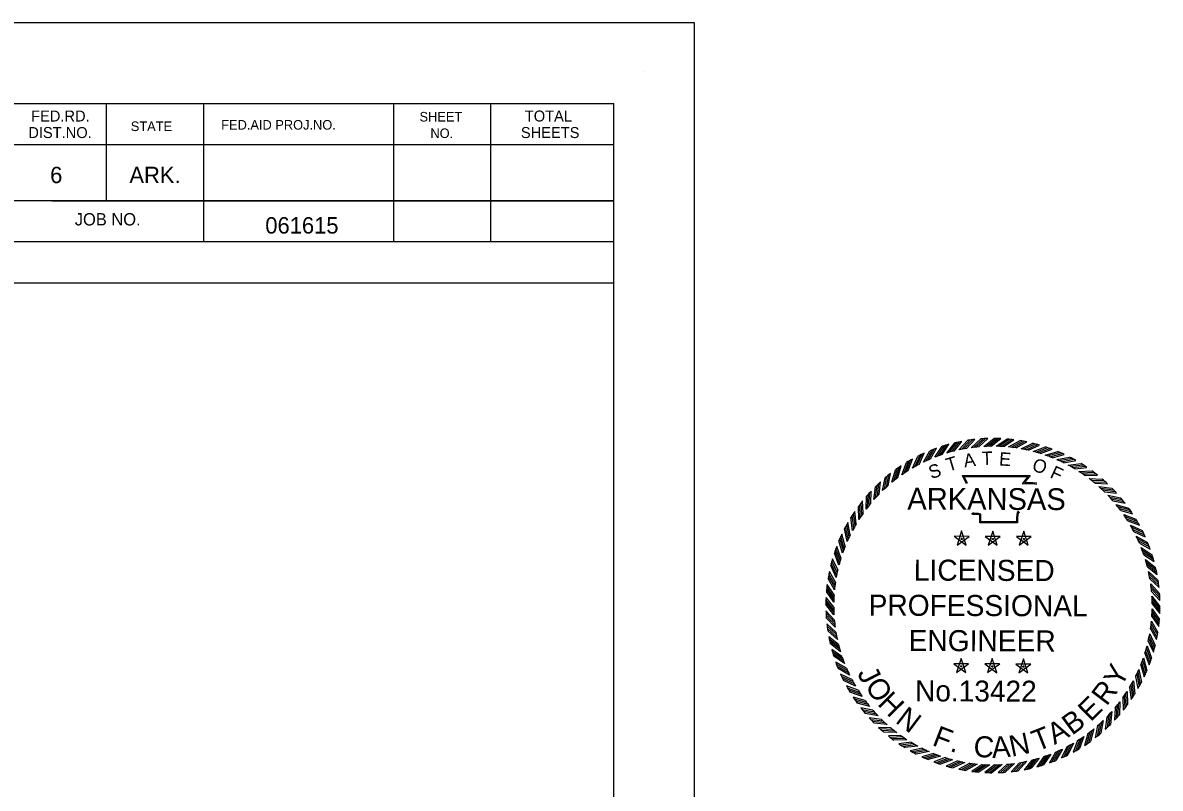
# Model space of a CAD drawing. Extents: x 759422 to 1448857, y 1662254 to 2059437.
# Drawn here: x 1448448.5 to 1448854.7, y 2059163.3 to 2059436.5 of the extents above; entities that cross this region are included whole.
import ezdxf

# ---------------------------------------------------------------- set-up
doc = ezdxf.new("R2010")
doc.units = 0
doc.layers.add('1', color=7, linetype='Continuous')
doc.layers.add('Default', color=7, linetype='Continuous')

# ---------------------------------------------------------------- blocks, each defined once
blk = doc.blocks.new('STAR')
at = {"layer": 'Default'}
for p, q in [((0.0587, 0.0188), (-0.059, 0.0189)), ((-0.0589, 0.0188), (0.0363, -0.0505)), ((-0.0001, 0.0615), (-0.0366, -0.0504)), ((-0.0365, -0.0503), (0.0589, 0.0188)), ((-0.0085, 0), (0.009, 0)), ((0.0362, -0.0503), (0, 0.0617)), ((0, 0.0063), (0, -0.0085))]:
    blk.add_line(p, q, dxfattribs=at)
blk = doc.blocks.new('RP')
at = {"layer": 'Default'}
for p, q in [((-0.0781, 1.2656), (0.003, 1.33)), ((-0.058, 1.2667), (0.0216, 1.3299)), ((-0.0375, 1.2674), (0.0405, 1.3294)), ((-0.0176, 1.2679), (0.059, 1.3287))]:
    blk.add_line(p, q, dxfattribs=at)
for radius, start, end in [(1.268, 90.79335, 93.53072), (1.33, 87.45624, 89.86992)]:
    blk.add_arc((0, 0), radius, start, end, dxfattribs=at)

msp = doc.modelspace()

# ---------------------------------------------------------------- linework, layer by layer
at = {"layer": '1'}
for p, q in [((1448670.52, 2059419.23), (1448670.52, 2059419.23)), ((1447064.22, 2059407.69), (1448659.58, 2059407.69)), ((1448478.28, 2059407.69), (1448478.28, 2059372.99)), ((1448512.98, 2059407.69), (1448512.98, 2059358.29)), ((1448580.88, 2059407.69), (1448580.88, 2059358.29)), ((1448615.58, 2059407.69), (1448615.58, 2059358.29)), ((1448659.58, 2058365.37), (1448659.58, 2059407.69)), ((1448659.58, 2059392.99), (1448444.08, 2059392.99)), ((1448659.58, 2059393.09), (1448659.58, 2059393.09)), ((1448659.58, 2059372.99), (1448444.08, 2059372.99)), ((1448458.88, 2059372.99), (1448659.58, 2059372.99)), ((1448659.58, 2059358.29), (1448248.28, 2059358.29)), ((1448444.08, 2059343.69), (1448659.58, 2059343.69))]:
    msp.add_line(p, q, dxfattribs=at)
msp.add_lwpolyline([(1448688.42, 2059436.53), (1446988.42, 2059436.53), (1446988.42, 2058336.53), (1448688.42, 2058336.53)], close=True, dxfattribs=at)
at = {"layer": 'Default'}
for points in [[(1448785.51, 2059271.98), (1448784.12, 2059275), (1448808.25, 2059274.93), (1448806.22, 2059272.41), (1448807.86, 2059272.42), (1448809.23, 2059272.43), (1448810.6, 2059272.28)], [(1448785.85, 2059272.13), (1448784.72, 2059274.62), (1448807.45, 2059274.55), (1448805.42, 2059272.02), (1448807.87, 2059272.04), (1448809.21, 2059272.05), (1448810.56, 2059271.9)], [(1448804.4, 2059261.8), (1448803.99, 2059261.47), (1448803.85, 2059260.97), (1448803.71, 2059259.72), (1448803.7, 2059258.05), (1448790.24, 2059258.09), (1448790.24, 2059260.35), (1448790.25, 2059260.85), (1448789.7, 2059261.01), (1448787.78, 2059261.02), (1448787.45, 2059261.54)], [(1448804.16, 2059262.1), (1448803.65, 2059261.69), (1448803.47, 2059261.04), (1448803.33, 2059259.74), (1448803.32, 2059258.43), (1448790.62, 2059258.48), (1448790.63, 2059260.34), (1448790.63, 2059261.13), (1448789.76, 2059261.4), (1448787.99, 2059261.4), (1448787.77, 2059261.75)]]:
    msp.add_lwpolyline(points, dxfattribs=at)

# ---------------------------------------------------------------- block references
for name, p, xscale, yscale, rotation in [('RP', (1448794.94, 2059228.53), 44.855502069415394, 44.85550206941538, 13.304199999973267), ('RP', (1448794.94, 2059228.53), 44.855502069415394, 44.855502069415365, 8.804199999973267), ('RP', (1448794.94, 2059228.53), 44.85550206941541, 44.85550206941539, 4.304199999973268), ('RP', (1448794.94, 2059228.53), 44.8555020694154, 44.85550206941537, -0.19580000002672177), ('RP', (1448794.94, 2059228.53), 44.8555020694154, 44.85550206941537, -4.695800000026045), ('RP', (1448794.94, 2059228.53), 44.85550206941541, 44.85550206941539, -9.195800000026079), ('RP', (1448794.94, 2059228.53), 44.855502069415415, 44.85550206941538, -13.695800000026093), ('RP', (1448794.94, 2059228.53), 44.85550206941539, 44.85550206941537, 22.30419999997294), ('RP', (1448794.94, 2059228.53), 44.855502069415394, 44.85550206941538, 17.80419999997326), ('RP', (1448794.94, 2059228.53), 44.85550206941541, 44.85550206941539, -18.195800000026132), ('RP', (1448794.94, 2059228.53), 44.8555020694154, 44.85550206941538, -22.69580000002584), ('RP', (1448794.94, 2059228.53), 44.855502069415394, 44.85550206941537, -27.19580000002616), ('RP', (1448794.94, 2059228.53), 44.85550206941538, 44.85550206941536, 31.30419999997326), ('RP', (1448794.94, 2059228.53), 44.855502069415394, 44.855502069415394, 26.804199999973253), ('RP', (1448794.94, 2059228.53), 44.85550206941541, 44.8555020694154, -31.695800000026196), ('RP', (1448794.94, 2059228.53), 44.85550206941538, 44.85550206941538, 40.304199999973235), ('RP', (1448794.94, 2059228.53), 44.85550206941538, 44.85550206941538, 35.80419999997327), ('RP', (1448794.94, 2059228.53), 44.8555020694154, 44.855502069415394, -36.195800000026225), ('RP', (1448794.94, 2059228.53), 44.85550206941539, 44.8555020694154, -40.69580000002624), ('RP', (1448794.94, 2059228.53), 44.85550206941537, 44.855502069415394, 44.80419999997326), ('RP', (1448794.94, 2059228.53), 44.85550206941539, 44.85550206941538, -45.195800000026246), ('RP', (1448794.94, 2059228.53), 44.8555020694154, 44.8555020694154, 49.304199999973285), ('RP', (1448794.94, 2059228.53), 44.85550206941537, 44.85550206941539, -49.695800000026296), ('RP', (1448794.94, 2059228.53), 44.8555020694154, 44.85550206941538, 53.804199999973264), ('RP', (1448794.94, 2059228.53), 44.85550206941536, 44.855502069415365, -54.1958000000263), ('RP', (1448794.94, 2059228.53), 44.85550206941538, 44.85550206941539, 58.304199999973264), ('RP', (1448794.94, 2059228.53), 44.85550206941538, 44.85550206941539, -58.695800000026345), ('RP', (1448794.94, 2059228.53), 44.85550206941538, 44.855502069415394, 62.804199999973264), ('STAR', (1448783.76, 2059252.39), 44.8555020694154, 44.85550206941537, -0.19580000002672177), ('STAR', (1448794.86, 2059252.35), 44.8555020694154, 44.85550206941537, -0.19580000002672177), ('STAR', (1448805.95, 2059252.31), 44.8555020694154, 44.85550206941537, -0.19580000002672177), ('RP', (1448794.94, 2059228.53), 44.85550206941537, 44.85550206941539, -63.19580000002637), ('RP', (1448794.94, 2059228.53), 44.85550206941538, 44.8555020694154, 67.30419999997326), ('RP', (1448794.94, 2059228.53), 44.85550206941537, 44.85550206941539, -67.6958000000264), ('RP', (1448794.94, 2059228.53), 44.85550206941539, 44.855502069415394, 71.80419999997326), ('RP', (1448794.94, 2059228.53), 44.85550206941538, 44.8555020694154, -72.19580000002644), ('RP', (1448794.94, 2059228.53), 44.85550206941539, 44.85550206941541, 76.30419999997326), ('RP', (1448794.94, 2059228.53), 44.85550206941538, 44.85550206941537, -76.69580000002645), ('RP', (1448794.94, 2059228.53), 44.85550206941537, 44.8555020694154, 80.80419999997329), ('RP', (1448794.94, 2059228.53), 44.85550206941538, 44.8555020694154, -81.19580000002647), ('RP', (1448794.94, 2059228.53), 44.855502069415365, 44.85550206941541, 85.30419999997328), ('RP', (1448794.94, 2059228.53), 44.85550206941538, 44.855502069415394, -85.69580000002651), ('RP', (1448794.94, 2059228.53), 44.85550206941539, 44.85550206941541, 89.80419999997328), ('RP', (1448794.94, 2059228.53), 44.85550206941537, 44.8555020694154, -90.19580000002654), ('RP', (1448794.94, 2059228.53), 44.85550206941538, 44.85550206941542, 94.30419999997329), ('RP', (1448794.94, 2059228.53), 44.85550206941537, 44.85550206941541, -94.69580000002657), ('RP', (1448794.94, 2059228.53), 44.85550206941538, 44.855502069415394, 98.8041999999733), ('RP', (1448794.94, 2059228.53), 44.85550206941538, 44.855502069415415, -99.19580000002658), ('RP', (1448794.94, 2059228.53), 44.85550206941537, 44.8555020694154, 103.30419999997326), ('RP', (1448794.94, 2059228.53), 44.85550206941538, 44.8555020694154, -103.69580000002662), ('RP', (1448794.94, 2059228.53), 44.85550206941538, 44.85550206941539, -108.19580000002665), ('RP', (1448794.94, 2059228.53), 44.85550206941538, 44.855502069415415, 107.80419999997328), ('RP', (1448794.94, 2059228.53), 44.85550206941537, 44.85550206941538, 112.3041999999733), ('STAR', (1448783.6, 2059206.89), 44.8555020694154, 44.85550206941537, -0.19580000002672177), ('STAR', (1448794.7, 2059206.85), 44.8555020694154, 44.85550206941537, -0.19580000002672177), ('STAR', (1448805.8, 2059206.81), 44.8555020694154, 44.85550206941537, -0.19580000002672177), ('RP', (1448794.94, 2059228.53), 44.85550206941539, 44.855502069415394, -112.69580000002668), ('RP', (1448794.94, 2059228.53), 44.85550206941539, 44.8555020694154, 116.80419999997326), ('RP', (1448794.94, 2059228.53), 44.85550206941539, 44.85550206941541, -117.19580000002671), ('RP', (1448794.94, 2059228.53), 44.855502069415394, 44.85550206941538, 121.30419999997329), ('RP', (1448794.94, 2059228.53), 44.8555020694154, 44.8555020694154, -126.19580000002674), ('RP', (1448794.94, 2059228.53), 44.85550206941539, 44.8555020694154, -121.69580000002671), ('RP', (1448794.94, 2059228.53), 44.85550206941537, 44.85550206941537, 125.80419999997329), ('RP', (1448794.94, 2059228.53), 44.85550206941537, 44.85550206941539, 130.3041999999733), ('RP', (1448794.94, 2059228.53), 44.85550206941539, 44.85550206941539, -130.6958000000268), ('RP', (1448794.94, 2059228.53), 44.855502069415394, 44.85550206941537, 134.80419999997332), ('RP', (1448794.94, 2059228.53), 44.85550206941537, 44.855502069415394, -135.19580000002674), ('RP', (1448794.94, 2059228.53), 44.85550206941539, 44.85550206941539, 139.30419999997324), ('RP', (1448794.94, 2059228.53), 44.85550206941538, 44.85550206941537, -139.69580000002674), ('RP', (1448794.94, 2059228.53), 44.85550206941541, 44.855502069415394, 143.8041999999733), ('RP', (1448794.94, 2059228.53), 44.85550206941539, 44.85550206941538, 148.3041999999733), ('RP', (1448794.94, 2059228.53), 44.85550206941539, 44.85550206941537, -148.69580000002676), ('RP', (1448794.94, 2059228.53), 44.85550206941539, 44.855502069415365, -144.19580000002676), ('RP', (1448794.94, 2059228.53), 44.8555020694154, 44.855502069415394, 152.8041999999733), ('RP', (1448794.94, 2059228.53), 44.85550206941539, 44.85550206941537, -153.1958000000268), ('RP', (1448794.94, 2059228.53), 44.8555020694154, 44.85550206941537, 157.3041999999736), ('RP', (1448794.94, 2059228.53), 44.85550206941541, 44.85550206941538, 161.80419999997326), ('RP', (1448794.94, 2059228.53), 44.855502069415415, 44.85550206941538, 166.3041999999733), ('RP', (1448794.94, 2059228.53), 44.855502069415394, 44.85550206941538, -166.69580000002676), ('RP', (1448794.94, 2059228.53), 44.855502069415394, 44.85550206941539, -162.19580000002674), ('RP', (1448794.94, 2059228.53), 44.8555020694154, 44.85550206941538, -157.6958000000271), ('RP', (1448794.94, 2059228.53), 44.8555020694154, 44.855502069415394, 170.8041999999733), ('RP', (1448794.94, 2059228.53), 44.8555020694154, 44.85550206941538, 175.3041999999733), ('RP', (1448794.94, 2059228.53), 44.85550206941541, 44.85550206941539, 179.8041999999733), ('RP', (1448794.94, 2059228.53), 44.8555020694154, 44.85550206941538, -175.69580000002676), ('RP', (1448794.94, 2059228.53), 44.85550206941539, 44.85550206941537, -171.19580000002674)]:
    msp.add_blockref(name, p, dxfattribs=dict(at, xscale=xscale, yscale=yscale, rotation=rotation))

# ---------------------------------------------------------------- texts
at = {"layer": '1'}
for s, height, p in [('FED.RD.', 3.91, (1448451.47, 2059401.29)), ('TOTAL', 3.91, (1448627.77, 2059401.29)), ('STATE', 3.42, (1448487.07, 2059397.89)), ('FED.AID PROJ.NO.', 3.42, (1448519.37, 2059398.39)), ('SHEET', 3.42, (1448590.17, 2059401.29)), ('DIST.NO.', 3.91, (1448450.47, 2059395.39)), ('NO.', 3.42, (1448594.07, 2059395.39)), ('SHEETS', 3.91, (1448626.37, 2059395.39)), ('6', 5.86, (1448458.27, 2059379.29)), ('ARK.', 5.861, (1448486.57, 2059379.29)), ('JOB NO.', 4.396, (1448467.07, 2059364.19)), ('061615', 5.862, (1448535.1, 2059361.29))]:
    msp.add_text(s, height=height, dxfattribs=at).set_placement(p)
at = {"layer": 'Default'}
for s, height, rotation, p in [('T', 4.76, 1.2831, (1448790.94, 2059278.71)), ('E', 4.76, 356.4762, (1448797.03, 2059278.55)), ('S', 4.76, 19.5768, (1448772.95, 2059273.6)), ('T', 4.76, 16.7057, (1448779.01, 2059276.3)), ('A', 4.76, 8.483, (1448784.79, 2059277.79)), ('O', 4.76, 341.026, (1448808.58, 2059276.87)), ('F', 4.76, 335.167, (1448814.99, 2059274.34)), ('ARKANSAS', 7.767, 359.8042, (1448764.36, 2059262.8)), ('LICENSED', 7.52, 359.8042, (1448766.68, 2059237.44)), ('PROFESSIONAL', 7.5196, 359.8042, (1448750.53, 2059224.92)), ('ENGINEER', 7.52, 359.8042, (1448764.81, 2059212.3)), ('J', 7.52, 297.2813, (1448746.33, 2059204.36)), ('Y', 7.52, 62.5392, (1448840.78, 2059199.02)), ('O', 7.52, 304.1899, (1448749, 2059199.75)), ('No.13422', 7.49, 359.8042, (1448767.12, 2059194.36)), ('H', 7.52, 314.7447, (1448753.43, 2059193.27)), ('R', 7.52, 52.7437, (1448835.53, 2059192.4)), ('E', 7.52, 44.306, (1448829.8, 2059186.8)), ('N', 7.52, 322.9417, (1448759.78, 2059186.98)), ('B', 7.52, 36.505, (1448823.17, 2059182.01)), ('F', 7.52, 339.0288, (1448772.91, 2059178.84)), ('T', 7.52, 21.4329, (1448810.67, 2059176.38)), ('A', 7.52, 28.8562, (1448816.92, 2059178.73)), ('C', 7.52, 356.1028, (1448787.83, 2059174.62)), ('A', 7.52, 3.9092, (1448794.72, 2059174.12)), ('N', 7.52, 12.0703, (1448801.6, 2059174.51)), ('.', 7.52, 344.7037, (1448779.32, 2059176.62))]:
    msp.add_text(s, height=height, rotation=rotation, dxfattribs=at).set_placement(p)

doc.saveas('drawing.dxf')
